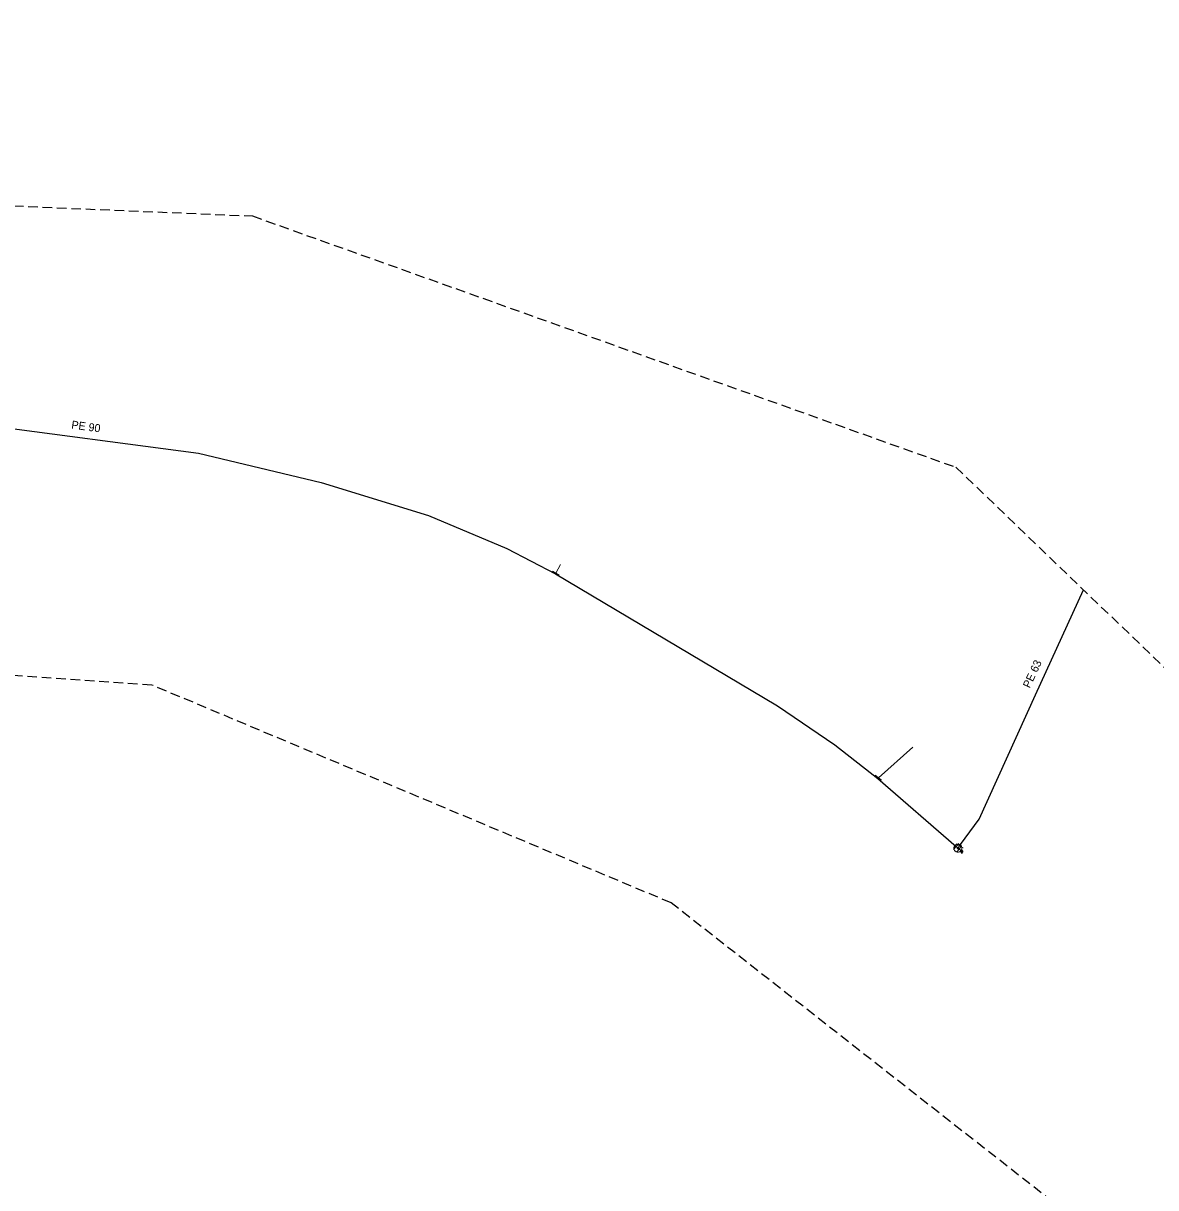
# Model space of a CAD drawing. Extents: x -692311 to -690519, y -971696 to -970899.
# Drawn here: x -690995.8 to -690854.3, y -971405.3 to -971259.8 of the extents above; entities that cross this region are included whole.
import ezdxf

# ---------------------------------------------------------------- set-up
doc = ezdxf.new("R2010")
doc.units = 0
doc.header["$LTSCALE"] = 0.4
doc.linetypes.add('MEDIUM_DASHED', pattern=[4.5, 3, -1.5])
for name, color, linetype, lineweight in [('1', 7, 'MEDIUM_DASHED', 25), ('13', 7, 'Continuous', 13), ('14', 7, 'Continuous', 13), ('17', 7, 'Continuous', 25), ('34', 7, 'Continuous', 13), ('47', 7, 'Continuous', 13), ('9', 7, 'Continuous', 13)]:
    doc.layers.add(name, color=color, linetype=linetype, lineweight=lineweight)

msp = doc.modelspace()

# ---------------------------------------------------------------- linework, layer by layer
at = {"layer": '1'}
msp.add_lwpolyline([(-691582.607, -971118.48), (-691415.135, -971114.294), (-691341.865, -971221.058), (-691239.288, -971223.151), (-691166.019, -971275.486), (-690967.145, -971283.86), (-690879.221, -971315.261), (-690772.457, -971417.838), (-690699.188, -971434.585), (-690602.891, -971597.872), (-690519.155, -971629.273), (-690531.715, -971696.262), (-690636.386, -971646.02), (-690749.43, -971493.201), (-690789.205, -971468.08), (-690914.809, -971369.69), (-690979.705, -971342.475), (-691195.326, -971327.822), (-691262.316, -971283.86), (-691377.453, -971285.953), (-691463.283, -971177.096)], dxfattribs=at)
at = {"layer": '13'}
for p, q in [((-690929.224, -971328.492), (-690928.64, -971327.421)), ((-690888.914, -971354.058), (-690884.62, -971350.239))]:
    msp.add_line(p, q, dxfattribs=at)
at = {"layer": '14'}
for p, q in [((-690929.27, -971328.57), (-690929.224, -971328.492)), ((-690888.969, -971354.129), (-690888.914, -971354.058)), ((-690878.969, -971362.85), (-690878.828, -971362.954)), ((-690878.828, -971362.954), (-690878.48, -971363.27))]:
    msp.add_line(p, q, dxfattribs=at)
msp.add_lwpolyline([(-690879.19, -971362.64), (-690878.969, -971362.85), (-690878.763, -971362.566)], dxfattribs=at)
at = {"layer": '17'}
for points in [[(-691151.21, -971301.78), (-691123.09, -971303.809), (-691104.3, -971305.109), (-691088.699, -971306.41), (-691069.219, -971307.44), (-691052.96, -971307.879), (-691030.6, -971308.21), (-691023.1, -971308.469), (-691001.05, -971309.92), (-690973.89, -971313.5), (-690958.55, -971317.18), (-690945.149, -971321.28), (-690935.34, -971325.399), (-690929.27, -971328.57), (-690915.59, -971336.68), (-690901.5, -971345.059), (-690894.34, -971349.93), (-690888.969, -971354.129), (-690879.19, -971362.64)], [(-690878.763, -971362.566), (-690878.67, -971362.399), (-690876.329, -971359.219), (-690869.27, -971343.71), (-690863.264, -971330.593)]]:
    msp.add_lwpolyline(points, dxfattribs=at)
at = {"layer": '34'}
for p, q in [((-690929.654, -971328.237), (-690928.794, -971328.747)), ((-690889.308, -971353.75), (-690888.52, -971354.366)), ((-690878.862, -971362.262), (-690879.518, -971363.016)), ((-690879.198, -971362.32), (-690878.328, -971362.812)), ((-690878.532, -971362.55), (-690879.123, -971363.357))]:
    msp.add_line(p, q, dxfattribs=at)
at = {"layer": '47'}
for points in [[(-690878.607, -971363.195), (-690878.573, -971363.155), (-690878.543, -971363.112), (-690878.519, -971363.066), (-690878.498, -971363.018), (-690878.483, -971362.968), (-690878.473, -971362.916), (-690878.47, -971362.864), (-690878.471, -971362.812), (-690878.477, -971362.76), (-690878.489, -971362.709), (-690878.506, -971362.659), (-690878.529, -971362.612), (-690878.556, -971362.568), (-690878.588, -971362.526), (-690878.623, -971362.488), (-690878.663, -971362.454), (-690878.706, -971362.424), (-690878.753, -971362.399), (-690878.8, -971362.379), (-690878.85, -971362.364), (-690878.902, -971362.354), (-690878.955, -971362.35), (-690879.007, -971362.351), (-690879.058, -971362.357), (-690879.109, -971362.37), (-690879.159, -971362.387), (-690879.206, -971362.409), (-690879.25, -971362.437), (-690879.292, -971362.469), (-690879.33, -971362.504), (-690879.364, -971362.544), (-690879.394, -971362.587), (-690879.42, -971362.633), (-690879.439, -971362.681), (-690879.454, -971362.731), (-690879.464, -971362.783), (-690879.469, -971362.835), (-690879.468, -971362.887), (-690879.461, -971362.939), (-690879.448, -971362.99), (-690879.431, -971363.04), (-690879.409, -971363.087), (-690879.381, -971363.131), (-690879.349, -971363.173), (-690879.314, -971363.211), (-690879.274, -971363.245), (-690879.231, -971363.275), (-690879.186, -971363.3), (-690879.137, -971363.32), (-690879.087, -971363.335), (-690879.035, -971363.345), (-690878.984, -971363.349), (-690878.931, -971363.348), (-690878.879, -971363.341), (-690878.828, -971363.329), (-690878.778, -971363.312), (-690878.732, -971363.29), (-690878.687, -971363.262), (-690878.645, -971363.23)], [(-690878.909, -971362.906), (-690878.903, -971362.9), (-690878.899, -971362.892), (-690878.895, -971362.885), (-690878.891, -971362.877), (-690878.889, -971362.869), (-690878.888, -971362.86), (-690878.886, -971362.852), (-690878.887, -971362.843), (-690878.888, -971362.835), (-690878.89, -971362.826), (-690878.893, -971362.818), (-690878.897, -971362.81), (-690878.901, -971362.803), (-690878.905, -971362.796), (-690878.912, -971362.79), (-690878.918, -971362.784), (-690878.926, -971362.78), (-690878.933, -971362.776), (-690878.941, -971362.772), (-690878.949, -971362.77), (-690878.958, -971362.769), (-690878.966, -971362.767), (-690878.975, -971362.768), (-690878.984, -971362.769), (-690878.992, -971362.771), (-690879, -971362.774), (-690879.008, -971362.778), (-690879.015, -971362.782), (-690879.022, -971362.786), (-690879.028, -971362.793), (-690879.034, -971362.799), (-690879.038, -971362.807), (-690879.042, -971362.814), (-690879.046, -971362.822), (-690879.048, -971362.83), (-690879.05, -971362.838), (-690879.051, -971362.847), (-690879.05, -971362.856), (-690879.049, -971362.865), (-690879.047, -971362.873), (-690879.044, -971362.881), (-690879.04, -971362.889), (-690879.036, -971362.896), (-690879.032, -971362.903), (-690879.025, -971362.909), (-690879.019, -971362.915), (-690879.011, -971362.919), (-690879.004, -971362.923), (-690878.996, -971362.927), (-690878.988, -971362.929), (-690878.98, -971362.931), (-690878.971, -971362.932), (-690878.962, -971362.931), (-690878.954, -971362.93), (-690878.945, -971362.928), (-690878.937, -971362.925), (-690878.929, -971362.921), (-690878.922, -971362.917), (-690878.915, -971362.913)]]:
    msp.add_lwpolyline(points, close=True, dxfattribs=at)
at = {"layer": '9'}
msp.add_line((-690878.481, -971363.397), (-690878.481, -971363.522), dxfattribs=at)
for points in [[(-690878.607, -971363.269), (-690878.606, -971363.282), (-690878.604, -971363.295), (-690878.601, -971363.308), (-690878.596, -971363.32), (-690878.59, -971363.332), (-690878.583, -971363.343), (-690878.575, -971363.353), (-690878.565, -971363.363), (-690878.555, -971363.371), (-690878.544, -971363.378), (-690878.532, -971363.384), (-690878.52, -971363.389), (-690878.507, -971363.392), (-690878.494, -971363.394), (-690878.481, -971363.397), (-690878.468, -971363.396), (-690878.455, -971363.394), (-690878.442, -971363.391), (-690878.43, -971363.386), (-690878.418, -971363.38), (-690878.407, -971363.373), (-690878.397, -971363.365), (-690878.387, -971363.355), (-690878.379, -971363.345), (-690878.372, -971363.334), (-690878.366, -971363.322), (-690878.361, -971363.31), (-690878.358, -971363.297), (-690878.356, -971363.284), (-690878.354, -971363.271), (-690878.355, -971363.258), (-690878.357, -971363.245), (-690878.36, -971363.232), (-690878.365, -971363.22), (-690878.371, -971363.208), (-690878.378, -971363.197), (-690878.386, -971363.187), (-690878.396, -971363.177), (-690878.406, -971363.169), (-690878.417, -971363.162), (-690878.429, -971363.156), (-690878.441, -971363.151), (-690878.454, -971363.148), (-690878.467, -971363.146), (-690878.48, -971363.144), (-690878.493, -971363.144), (-690878.506, -971363.146), (-690878.519, -971363.149), (-690878.531, -971363.154), (-690878.543, -971363.16), (-690878.554, -971363.167), (-690878.564, -971363.175), (-690878.574, -971363.185), (-690878.582, -971363.195), (-690878.589, -971363.206), (-690878.595, -971363.218), (-690878.6, -971363.23), (-690878.603, -971363.243), (-690878.605, -971363.256)], [(-690878.587, -971363.269), (-690878.587, -971363.28), (-690878.585, -971363.291), (-690878.582, -971363.302), (-690878.578, -971363.312), (-690878.573, -971363.322), (-690878.567, -971363.331), (-690878.56, -971363.34), (-690878.552, -971363.348), (-690878.543, -971363.355), (-690878.534, -971363.361), (-690878.524, -971363.366), (-690878.514, -971363.37), (-690878.503, -971363.373), (-690878.492, -971363.375), (-690878.481, -971363.375), (-690878.47, -971363.377), (-690878.459, -971363.375), (-690878.448, -971363.372), (-690878.438, -971363.368), (-690878.428, -971363.363), (-690878.419, -971363.357), (-690878.41, -971363.35), (-690878.402, -971363.342), (-690878.395, -971363.333), (-690878.389, -971363.324), (-690878.384, -971363.314), (-690878.38, -971363.304), (-690878.377, -971363.293), (-690878.375, -971363.282), (-690878.374, -971363.271), (-690878.374, -971363.26), (-690878.376, -971363.249), (-690878.379, -971363.238), (-690878.383, -971363.228), (-690878.388, -971363.218), (-690878.394, -971363.209), (-690878.401, -971363.2), (-690878.409, -971363.192), (-690878.418, -971363.185), (-690878.427, -971363.179), (-690878.437, -971363.174), (-690878.447, -971363.17), (-690878.458, -971363.167), (-690878.469, -971363.165), (-690878.48, -971363.164), (-690878.491, -971363.163), (-690878.502, -971363.165), (-690878.513, -971363.168), (-690878.523, -971363.172), (-690878.533, -971363.177), (-690878.542, -971363.183), (-690878.551, -971363.19), (-690878.559, -971363.198), (-690878.566, -971363.207), (-690878.572, -971363.216), (-690878.577, -971363.226), (-690878.581, -971363.236), (-690878.584, -971363.247), (-690878.586, -971363.258)], [(-690878.568, -971363.269), (-690878.567, -971363.278), (-690878.566, -971363.287), (-690878.563, -971363.296), (-690878.56, -971363.304), (-690878.556, -971363.312), (-690878.551, -971363.32), (-690878.545, -971363.327), (-690878.539, -971363.333), (-690878.532, -971363.339), (-690878.524, -971363.344), (-690878.516, -971363.348), (-690878.508, -971363.351), (-690878.499, -971363.354), (-690878.49, -971363.355), (-690878.481, -971363.358), (-690878.472, -971363.357), (-690878.463, -971363.356), (-690878.454, -971363.353), (-690878.446, -971363.35), (-690878.438, -971363.346), (-690878.43, -971363.341), (-690878.423, -971363.335), (-690878.417, -971363.329), (-690878.411, -971363.322), (-690878.406, -971363.314), (-690878.402, -971363.306), (-690878.399, -971363.298), (-690878.396, -971363.289), (-690878.395, -971363.28), (-690878.393, -971363.271), (-690878.394, -971363.262), (-690878.395, -971363.253), (-690878.398, -971363.244), (-690878.401, -971363.236), (-690878.405, -971363.228), (-690878.41, -971363.22), (-690878.416, -971363.213), (-690878.422, -971363.207), (-690878.429, -971363.201), (-690878.437, -971363.196), (-690878.445, -971363.192), (-690878.453, -971363.189), (-690878.462, -971363.186), (-690878.471, -971363.185), (-690878.48, -971363.183), (-690878.489, -971363.183), (-690878.498, -971363.184), (-690878.507, -971363.187), (-690878.515, -971363.19), (-690878.523, -971363.194), (-690878.531, -971363.199), (-690878.538, -971363.205), (-690878.544, -971363.211), (-690878.55, -971363.218), (-690878.555, -971363.226), (-690878.559, -971363.234), (-690878.562, -971363.242), (-690878.565, -971363.251), (-690878.566, -971363.26)], [(-690878.548, -971363.269), (-690878.548, -971363.276), (-690878.546, -971363.283), (-690878.545, -971363.29), (-690878.542, -971363.296), (-690878.539, -971363.302), (-690878.535, -971363.308), (-690878.531, -971363.314), (-690878.526, -971363.319), (-690878.52, -971363.323), (-690878.514, -971363.327), (-690878.508, -971363.33), (-690878.502, -971363.333), (-690878.495, -971363.334), (-690878.488, -971363.336), (-690878.481, -971363.337), (-690878.474, -971363.338), (-690878.467, -971363.336), (-690878.46, -971363.335), (-690878.454, -971363.332), (-690878.447, -971363.329), (-690878.442, -971363.325), (-690878.436, -971363.321), (-690878.431, -971363.316), (-690878.427, -971363.31), (-690878.423, -971363.304), (-690878.42, -971363.298), (-690878.417, -971363.292), (-690878.415, -971363.285), (-690878.414, -971363.278), (-690878.413, -971363.271), (-690878.413, -971363.264), (-690878.414, -971363.257), (-690878.416, -971363.25), (-690878.419, -971363.244), (-690878.422, -971363.237), (-690878.426, -971363.232), (-690878.43, -971363.226), (-690878.435, -971363.221), (-690878.441, -971363.217), (-690878.446, -971363.213), (-690878.453, -971363.21), (-690878.459, -971363.207), (-690878.466, -971363.205), (-690878.473, -971363.204), (-690878.48, -971363.203), (-690878.487, -971363.202), (-690878.494, -971363.203), (-690878.501, -971363.205), (-690878.507, -971363.208), (-690878.513, -971363.211), (-690878.519, -971363.215), (-690878.525, -971363.219), (-690878.53, -971363.224), (-690878.534, -971363.23), (-690878.538, -971363.235), (-690878.541, -971363.242), (-690878.544, -971363.248), (-690878.545, -971363.255), (-690878.547, -971363.262)], [(-690878.528, -971363.269), (-690878.528, -971363.274), (-690878.527, -971363.279), (-690878.526, -971363.284), (-690878.524, -971363.288), (-690878.522, -971363.293), (-690878.519, -971363.297), (-690878.516, -971363.3), (-690878.512, -971363.304), (-690878.509, -971363.307), (-690878.505, -971363.31), (-690878.5, -971363.312), (-690878.496, -971363.314), (-690878.491, -971363.315), (-690878.486, -971363.316), (-690878.481, -971363.316), (-690878.476, -971363.318), (-690878.471, -971363.317), (-690878.466, -971363.316), (-690878.462, -971363.314), (-690878.457, -971363.312), (-690878.453, -971363.309), (-690878.449, -971363.306), (-690878.446, -971363.302), (-690878.443, -971363.299), (-690878.44, -971363.295), (-690878.438, -971363.29), (-690878.436, -971363.286), (-690878.435, -971363.281), (-690878.434, -971363.276), (-690878.434, -971363.271), (-690878.433, -971363.266), (-690878.434, -971363.261), (-690878.435, -971363.256), (-690878.437, -971363.252), (-690878.439, -971363.247), (-690878.442, -971363.243), (-690878.445, -971363.239), (-690878.448, -971363.236), (-690878.452, -971363.233), (-690878.456, -971363.23), (-690878.461, -971363.228), (-690878.465, -971363.226), (-690878.47, -971363.225), (-690878.475, -971363.224), (-690878.48, -971363.223), (-690878.485, -971363.222), (-690878.49, -971363.223), (-690878.495, -971363.224), (-690878.499, -971363.226), (-690878.504, -971363.228), (-690878.508, -971363.231), (-690878.511, -971363.234), (-690878.515, -971363.237), (-690878.518, -971363.241), (-690878.521, -971363.245), (-690878.523, -971363.25), (-690878.525, -971363.254), (-690878.526, -971363.259), (-690878.527, -971363.264)], [(-690878.508, -971363.269), (-690878.508, -971363.272), (-690878.508, -971363.275), (-690878.507, -971363.277), (-690878.506, -971363.28), (-690878.505, -971363.283), (-690878.503, -971363.285), (-690878.501, -971363.287), (-690878.499, -971363.289), (-690878.497, -971363.291), (-690878.495, -971363.293), (-690878.492, -971363.294), (-690878.489, -971363.295), (-690878.487, -971363.296), (-690878.484, -971363.296), (-690878.481, -971363.296), (-690878.478, -971363.298), (-690878.475, -971363.298), (-690878.472, -971363.297), (-690878.47, -971363.296), (-690878.467, -971363.295), (-690878.465, -971363.293), (-690878.462, -971363.291), (-690878.46, -971363.289), (-690878.459, -971363.287), (-690878.457, -971363.285), (-690878.456, -971363.282), (-690878.455, -971363.279), (-690878.454, -971363.277), (-690878.454, -971363.274), (-690878.452, -971363.271), (-690878.453, -971363.268), (-690878.453, -971363.265), (-690878.454, -971363.262), (-690878.455, -971363.26), (-690878.456, -971363.257), (-690878.458, -971363.255), (-690878.459, -971363.252), (-690878.461, -971363.25), (-690878.464, -971363.249), (-690878.466, -971363.247), (-690878.469, -971363.246), (-690878.471, -971363.245), (-690878.474, -971363.244), (-690878.477, -971363.244), (-690878.48, -971363.242), (-690878.483, -971363.242), (-690878.486, -971363.242), (-690878.488, -971363.243), (-690878.491, -971363.244), (-690878.494, -971363.245), (-690878.496, -971363.247), (-690878.498, -971363.248), (-690878.5, -971363.25), (-690878.502, -971363.253), (-690878.504, -971363.255), (-690878.505, -971363.258), (-690878.506, -971363.26), (-690878.507, -971363.263), (-690878.507, -971363.266)], [(-690878.489, -971363.269), (-690878.489, -971363.27), (-690878.489, -971363.271), (-690878.488, -971363.271), (-690878.488, -971363.272), (-690878.488, -971363.273), (-690878.487, -971363.274), (-690878.487, -971363.274), (-690878.486, -971363.275), (-690878.486, -971363.275), (-690878.485, -971363.276), (-690878.484, -971363.276), (-690878.483, -971363.276), (-690878.483, -971363.277), (-690878.482, -971363.277), (-690878.481, -971363.277), (-690878.48, -971363.278), (-690878.479, -971363.278), (-690878.479, -971363.278), (-690878.478, -971363.278), (-690878.477, -971363.278), (-690878.476, -971363.277), (-690878.476, -971363.277), (-690878.475, -971363.276), (-690878.475, -971363.276), (-690878.474, -971363.275), (-690878.474, -971363.274), (-690878.473, -971363.273), (-690878.473, -971363.273), (-690878.473, -971363.272), (-690878.472, -971363.271), (-690878.472, -971363.27), (-690878.472, -971363.269), (-690878.472, -971363.269), (-690878.473, -971363.268), (-690878.473, -971363.267), (-690878.474, -971363.266), (-690878.474, -971363.266), (-690878.475, -971363.265), (-690878.475, -971363.265), (-690878.476, -971363.264), (-690878.477, -971363.264), (-690878.478, -971363.263), (-690878.478, -971363.263), (-690878.479, -971363.263), (-690878.48, -971363.262), (-690878.481, -971363.262), (-690878.482, -971363.261), (-690878.482, -971363.261), (-690878.483, -971363.262), (-690878.484, -971363.262), (-690878.485, -971363.263), (-690878.485, -971363.263), (-690878.486, -971363.264), (-690878.486, -971363.264), (-690878.487, -971363.265), (-690878.487, -971363.266), (-690878.487, -971363.267), (-690878.488, -971363.267), (-690878.488, -971363.268)]]:
    msp.add_lwpolyline(points, close=True, dxfattribs=at)
msp.add_lwpolyline([(-690878.45, -971363.488), (-690878.481, -971363.522), (-690878.512, -971363.486)], dxfattribs=at)

# ---------------------------------------------------------------- texts
at = {"layer": '1'}
for s, rotation, p in [('PE 90 ', 352, (-690989.818, -971310.405)), ('PE 63 ', 65, (-690869.998, -971342.934))]:
    msp.add_text(s, height=1, rotation=rotation, dxfattribs=at).set_placement(p)

doc.saveas('drawing.dxf')
